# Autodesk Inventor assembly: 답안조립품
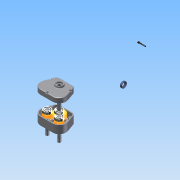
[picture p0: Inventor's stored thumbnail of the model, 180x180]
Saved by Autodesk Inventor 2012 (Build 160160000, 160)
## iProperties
Created: 2014-12
Part Number: 답안조립품
Document SubType Name: Assembly
Designer: Administrator
Author: Administrator
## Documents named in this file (14)
- C:\Documents and Settings\Administrator\바탕 화면\441208V1027\답안조립품.iam
- C:\Documents and Settings\Administrator\바탕 화면\441208V1027\본체.ipt
- C:\Documents and Settings\Administrator\바탕 화면\441208V1027\멈춤링.ipt
- C:\Documents and Settings\Administrator\바탕 화면\441208V1027\메인기어.ipt
- C:\Documents and Settings\Administrator\바탕 화면\441208V1027\메인축.ipt
- C:\Documents and Settings\Administrator\바탕 화면\441208V1027\베어링- 6202.ipt
- C:\Documents and Settings\Administrator\바탕 화면\441208V1027\베어링- 6203.ipt
- C:\Documents and Settings\Administrator\바탕 화면\441208V1027\서브기어.ipt
- C:\Documents and Settings\Administrator\바탕 화면\441208V1027\서브축.ipt
- C:\Documents and Settings\Administrator\바탕 화면\441208V1027\오일시일-D-15.ipt
- C:\Documents and Settings\Administrator\바탕 화면\441208V1027\오일시일-D-17.ipt
- C:\Documents and Settings\Administrator\바탕 화면\441208V1027\커버.ipt
- C:\Documents and Settings\Administrator\바탕 화면\441208V1027\키5x5.ipt
- C:\Documents and Settings\Administrator\바탕 화면\441208V1027\M 5 x 35.ipt
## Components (13 placed, 6 different names)
1. KS B 1336 17 x 1:1
2. KS B 2023 6202 - 15 x 35 x 11:1
3. KS B 2023 6203 - 17 x 40 x 12:1
4. KS B 2804 D D - 15 30 7:1
5. KS B 2804 D D - 17 30 8:1
6. KS B 1003 - 미터 M 5 x 35:1
7. KS B 2023 6202 - 15 x 35 x 11:2
8. KS B 2023 6203 - 17 x 40 x 12:2
9. KS B 2023 6203 - 17 x 40 x 12:3
10. KS B 2023 6203 - 17 x 40 x 12:4
11. KS B 1336 17 x 1:2
12. KS B 1336 17 x 1:3
13. KS B 2804 D D - 15 30 7:2
